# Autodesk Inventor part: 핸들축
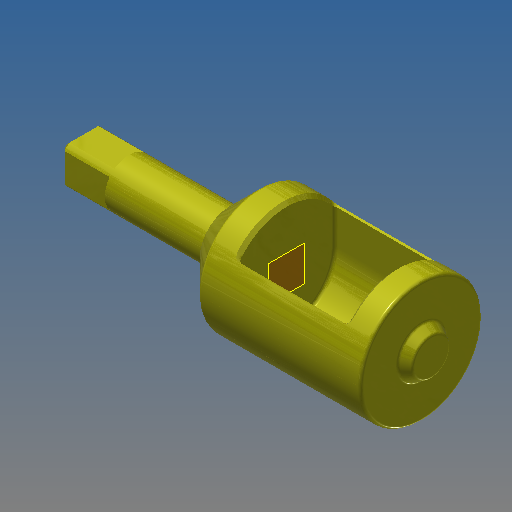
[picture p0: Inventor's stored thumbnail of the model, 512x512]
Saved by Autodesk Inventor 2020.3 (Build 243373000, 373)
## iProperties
Created: 2018-01
Part Number: 핸들축
Material: 강철, 연강
Document SubType Name: Modeling
Designer: mduedu
Density: 1 g/cm^3
Appearance: 노란색
Author: mduedu
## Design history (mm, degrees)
sketch "스케치1"
  geometry: L1 (0, 0)-(-109, 0); L2 (-46, -7.5)-(0, -7.5); L3 (0, -7.5)-(0, 0); L4 (-106, -19)-(-46, -19); L5 (-46, -19)-(-46, -7.5); L6 (-106, -7.5)-(-106, -19); L7 (-109, -5.768)-(-106, -7.5); L8 (-109, -5.768)-(-109, 0)
  constraints: 16 end point, 2 parallel, 1 horizontal, 1 vertical
  dimensions: "d8" = 15 diameter of L2 L1; "d43" = 46 distance between parallel lines of L3 L5; "d47" = 60 distance between parallel lines of L5 L6; "d63" = 3 distance between parallel lines of L6 L8; "d77" = 38 diameter of L4 L1; "d78" = 15 diameter of L6.start L1; "d79" = 30 deg angle of L1 L7
revolve "회전1" sketch "스케치1" stored, may be unused: angle "d9" = 90 deg
sketch "스케치4"
  geometry: L1 (-6, -6)-(-4.5, -6); L2 (6, -6)-(6, -4.5); L3 (6, 6)-(4.5, 6); L4 (-6, 6)-(-6, 4.5); L5 (-6, -6)-(6, 6); L6 (6, -6)-(-6, 6); L7 (-4.5, 6)-(-6, 6); L8 (-6, 4.5)-(-6, -4.5); L9 (-6, -4.5)-(-6, -6); L10 (-4.5, -6)-(4.5, -6); L11 (4.5, -6)-(6, -6); L12 (6, -4.5)-(6, 4.5); L13 (6, 4.5)-(6, 6); L14 (4.5, 6)-(-4.5, 6); C1 r 7.5 at (0, 0) reference; 2 further points
  constraints: 28 end point, 18 parallel, 9 perpendicular, 3 horizontal, 2 midpoint, 1 coincident, 11 other
  dimensions: "d20" = 12 distance of L4.start L3.start; "d21" = 12 distance of L3.start L2.start (= d20)
extrude "돌출2" cut sketch "스케치4" distance "d22" = 15; taper "d23" = 0 deg
chamfer "모따기2" distance "d24" = 1; stored, may be unused: second distance "d25" = 2, angle "d26" = 45 deg
sketch "스케치5"
  geometry: 2 further points
  constraints: 1 coincident
hole "구멍1" sketch "스케치5" at (5, 4.153) diameter "d27" = 2.459; stored, may be unused: countersink angle "d31" = 90 deg, drill point angle "d33" = 120 deg; dims "d28" = 6.9, "d29" = 4, "d30" = 2, "d32" = 8.4
node "작업 평면1"
sketch "스케치9"
  geometry: L1 (10, 4.153)-(10, 15.815); L2 (-20, 4.153)-(-20, 15.815); A1 r 15 centre (-5, 4.153) between (-20, 4.153) and (10, 4.153); A2 r 19 centre (-5, 4.153) between (10, 15.815) and (-20, 15.815) reference; 1 further point
  constraints: 4 end point, 4 point on circle, 2 tangent, 1 centre point, 1 coincident, 1 concentric, 1 parallel, 1 vertical
  dimensions: "d76" = 4 radial gap between concentric circles of A2 A1
extrude "돌출4" cut sketch "스케치9" distance "d73" = 34; taper "d74" = 0 deg
chamfer "모따기3" distance "d44" = 10; stored, may be unused: second distance "d45" = 2, angle "d46" = 45 deg
fillet "모깎기4" dims "d80" = 1
chamfer "모따기5" distance "d81" = 1; stored, may be unused: second distance "d82" = 2, angle "d83" = 45 deg
node "솔리드1"
other parameters: "d75" = -64
